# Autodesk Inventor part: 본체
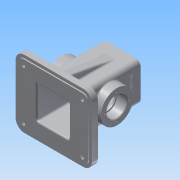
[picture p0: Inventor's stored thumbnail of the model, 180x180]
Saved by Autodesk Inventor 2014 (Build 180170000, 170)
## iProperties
Created: 2015-12
Part Number: 본체
Material: 알루미늄 6061
Document SubType Name: Modeling
Designer: Administrator
Density: 2.71 g/cm^3
Appearance: 알루미늄 - 평지
Mass: 913.38 g
Surface Area: 966.963 cm^2
Volume: 337.041 cm^3
Author: Administrator
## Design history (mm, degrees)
sketch "스케치1"
  geometry: L1 (32.5, 55)-(-32.5, 55); L2 (-32.5, 55)-(-32.5, -55); L3 (-32.5, -55)-(32.5, -55); L4 (32.5, -55)-(32.5, 55); L5 (32.5, 55)-(-32.5, -55); L6 (-32.5, 55)-(32.5, -55); 1 further point
  constraints: 12 end point, 2 midpoint, 2 parallel, 1 horizontal, 1 perpendicular
  dimensions: "d0" = 65 distance of L3.end L2.end; "d1" = 110 distance of L2.end L1.end
extrude "돌출1" new body sketch "스케치1" stored distance "d2" = 65; taper "d3" = 0 deg
sketch "스케치2"
  geometry: C1 r 20 at (32.5, 32.5); 1 further point
  constraints: 1 centre point, 1 coincident
  dimensions: "d4" = 40 diameter of C1
extrude "돌출2" join sketch "스케치2" distance "d5" = 10; taper "d6" = 0 deg
sketch "스케치3"
  geometry: L1 (50, 27.5)-(-55, 27.5); L2 (-55, 27.5)-(-55, -27.5); L3 (-55, -27.5)-(50, -27.5); L4 (50, -27.5)-(50, 27.5); L5 (-55, -32.5)-(-55, 32.5) reference; 3 further points
  constraints: 8 end point, 3 midpoint, 2 parallel, 1 horizontal, 1 horizontal alignment, 1 perpendicular
  dimensions: "d9" = 105 distance of L3.end L2.end; "d10" = 55 distance of L2.end L1.end
extrude "돌출3" cut sketch "스케치3" stored distance "d11" = 55; taper "d12" = 0 deg
sketch "스케치4"
  geometry: C1 r 20 at (0, 0) reference; C2 r 10.5 at (0, 0)
  constraints: 1 centre point, 1 coincident
  dimensions: "d13" = 21 diameter of C2
extrude "돌출4" cut sketch "스케치4" stored distance "d14" = 55; taper "d15" = 0 deg
sketch "스케치5"
  geometry: C1 r 27.5 at (-32.5, 55); 1 further point
  constraints: 1 centre point, 1 coincident
  dimensions: "d16" = 55 diameter of C1
extrude "돌출5" join sketch "스케치5" distance "d17" = 15; taper "d18" = 0 deg
sketch "스케치6" dims "d19" = 42
  geometry: C1 r 27.5 at (0, 0) reference; 2 further points
  constraints: 1 coincident, 1 vertical alignment, 2 other
hole "구멍1" sketch "스케치6" at (0, 21) diameter "d20" = 3.242; stored, may be unused: countersink angle "d24" = 90 deg, drill point angle "d26" = 118 deg; dims "d21" = 8, "d22" = 4, "d23" = 2, "d25" = 10
sketch "스케치7"
  geometry: C1 r 27.5 at (0, 0) reference; C2 r 17.5 at (0, 0)
  constraints: 1 centre point, 1 coincident
  dimensions: "d30" = 35 diameter of C2
extrude "돌출6" cut sketch "스케치7" distance "d31" = 17; taper "d32" = 0 deg
sketch "스케치8"
  geometry: C1 r 17.5 at (0, 0) reference; C2 r 15 at (0, 0)
  constraints: 1 centre point, 1 coincident
  dimensions: "d33" = 30 diameter of C2
extrude "돌출7" cut sketch "스케치8" stored distance "d34" = 17; taper "d35" = 0 deg
sketch "스케치11" dims "d36" = 29
  geometry: C1 r 20 at (0, 0) reference; 2 further points
  constraints: 1 coincident, 1 vertical alignment, 2 other
hole "구멍2" sketch "스케치11" at (0, 14.5) diameter "d37" = 2.459; stored, may be unused: countersink angle "d41" = 90 deg, drill point angle "d43" = 118 deg; dims "d38" = 8, "d39" = 4, "d40" = 2, "d42" = 10
node "작업 평면1"
sketch "스케치14"
  geometry: L1 (-65, 57.5)-(65, 57.5); L2 (65, 57.5)-(65, -57.5); L3 (65, -57.5)-(-65, -57.5); L4 (-65, -57.5)-(-65, 57.5); L5 (-65, 57.5)-(65, -57.5); L6 (65, 57.5)-(-65, -57.5); 1 further point
  constraints: 12 end point, 2 midpoint, 2 parallel, 1 horizontal, 1 perpendicular
  dimensions: "d50" = 130 distance of L2.end L3.end; "d51" = 115 distance of L1.end L2.end
extrude "돌출8" join sketch "스케치14" distance "d52" = 10; taper "d53" = 0 deg
sketch "스케치15"
  geometry: L1 (60, 52.5)-(-60, 52.5); L2 (-60, 52.5)-(-60, -52.5); L3 (-60, -52.5)-(60, -52.5); L4 (60, -52.5)-(60, 52.5); L5 (60, 52.5)-(-60, -52.5); L6 (-60, 52.5)-(60, -52.5); 1 further point
  constraints: 12 end point, 2 midpoint, 2 parallel, 1 horizontal, 1 perpendicular
  dimensions: "d54" = 120 distance of L3.end L2.end; "d55" = 105 distance of L2.end L1.end
extrude "돌출9" join sketch "스케치15" distance "d56" = 2; taper "d57" = 0 deg
fillet "모깎기1" dims "d59" = 15
sketch "스케치17"
  geometry: C1 r 7.5 at (-50, 42.5); C2 r 7.5 at (50, 42.5); C3 r 7.5 at (-50, -42.5); C4 r 7.5 at (50, -42.5); A1 r 15 centre (-50, 42.5) between (-50, 57.5) and (-65, 42.5) reference; A2 r 15 centre (-50, -42.5) between (-65, -42.5) and (-50, -57.5) reference; A3 r 15 centre (50, -42.5) between (50, -57.5) and (65, -42.5) reference; A4 r 15 centre (50, 42.5) between (65, 42.5) and (50, 57.5) reference; 1 further point
  constraints: 4 centre point, 4 coincident
  dimensions: "d60" = 15 diameter of C1; "d61" = 15 diameter of C2; "d62" = 15 diameter of C3; "d63" = 15 diameter of C4
extrude "돌출10" join sketch "스케치17" distance "d64" = 3; taper "d65" = 0 deg
sketch "스케치18"
  geometry: C1 r 7.5 at (0, 0) reference; C2 r 3 at (0, 0); 1 further point
  constraints: 1 centre point, 1 coincident
  dimensions: "d66" = 6 diameter of C2
extrude "돌출11" cut sketch "스케치18" stored distance "d67" = 3; taper "d68" = 0 deg
sketch "스케치19"
  geometry: C1 r 7.5 at (0, 0) reference; C2 r 3 at (0, 0); 1 further point
  constraints: 1 centre point, 1 coincident
  dimensions: "d69" = 6 diameter of C2
extrude "돌출12" cut sketch "스케치19" stored distance "d70" = 3; taper "d71" = 0 deg
sketch "스케치21"
  geometry: L1 (65, -20)-(55, -20) reference; L2 (55, -20)-(55, -32.5) reference; L3 (55, -32.5)-(-50, -32.5) reference; L4 (-50, -32.5)-(-50, -57.5) reference; L5 (-50, -57.5)-(-60, -57.5) reference; L6 (-60, -57.5)-(-60, -52.5) reference; L7 (-60, -52.5)-(-62, -52.5) reference; L8 (-62, -52.5)-(-62, 52.5) reference; L9 (-62, 52.5)-(-60, 52.5) reference; L10 (-60, 52.5)-(-60, 57.5) reference; L11 (-60, 57.5)-(-50, 57.5) reference; L12 (-50, 57.5)-(-50, 32.5) reference; L13 (-50, 32.5)-(55, 32.5) reference; L14 (55, 32.5)-(55, 20) reference; L15 (55, 20)-(65, 20) reference; L16 (65, 20)-(65, 15.73) reference; L17 (65, 15.73)-(55, 15.73) reference; L18 (55, 15.73)-(54.261, 14.5) reference; L19 (54.261, 14.5)-(55, 13.271) reference; L20 (55, 13.271)-(65, 13.271) reference; L21 (65, 13.271)-(65, 10.5) reference; L22 (65, 10.5)-(50, 10.5) reference; L23 (50, 10.5)-(50, 27.5) reference; L24 (50, 27.5)-(-50, 27.5) reference; L25 (-50, 27.5)-(-50, -27.5) reference; L26 (-50, -27.5)-(50, -27.5) reference; L27 (50, -27.5)-(50, -10.5) reference; L28 (50, -10.5)-(65, -10.5) reference; L29 (65, -10.5)-(65, -13.271) reference; L30 (65, -13.271)-(55, -13.271) reference; L31 (55, -13.271)-(54.261, -14.5) reference; L32 (54.261, -14.5)-(55, -15.73) reference; L33 (55, -15.73)-(65, -15.73) reference; L34 (65, -15.73)-(65, -20) reference; L35 (-50, 57.5)-(-50, 47.5); L36 (-50, 47.5)-(35.069, 32.5); 1 further point
  constraints: 4 end point, 2 point on line
  dimensions: "d77" = 10 distance of L11.end L35.end; "d78" = 80 deg angle of L12 L36
extrude "돌출13" join sketch "스케치21" stored distance "d79" = 15; taper "d80" = 0 deg
fillet "모깎기2" dims "d81" = 10
sketch "스케치22"
  geometry: L1 (-37.5, -22.621)-(-36.526, -21) reference; L2 (-36.526, -21)-(-37.5, -19.379) reference; L3 (-37.5, -19.379)-(-47.5, -19.379) reference; L4 (-47.5, -19.379)-(-47.5, -17.5) reference; L5 (-47.5, -17.5)-(-30.5, -17.5) reference; L6 (-30.5, -17.5)-(-30.5, -15) reference; L7 (-30.5, -15)-(-27.5, -15) reference; L8 (-27.5, -15)-(-27.5, -50) reference; L9 (-27.5, -50)-(27.5, -50) reference; L10 (27.5, -50)-(27.5, -15) reference; L11 (27.5, -15)-(30.5, -15) reference; L12 (30.5, -15)-(30.5, -17.5) reference; L13 (30.5, -17.5)-(47.5, -17.5) reference; L14 (47.5, -17.5)-(47.5, -19.379) reference; L15 (47.5, -19.379)-(37.5, -19.379) reference; L16 (37.5, -19.379)-(36.526, -21) reference; L17 (36.526, -21)-(37.5, -22.621) reference; L18 (37.5, -22.621)-(47.5, -22.621) reference; L19 (47.5, -22.621)-(47.5, -27.5) reference; L20 (47.5, -27.5)-(32.5, -27.5) reference; L21 (32.5, -27.5)-(32.5, -50) reference; L22 (32.5, -50)-(65, -50) reference; L23 (65, -50)-(65, -60) reference; L24 (65, -60)-(60, -60) reference; L25 (60, -60)-(60, -62) reference; L26 (60, -62)-(-60, -62) reference; L27 (-60, -62)-(-60, -60) reference; L28 (-60, -60)-(-65, -60) reference; L29 (-65, -60)-(-65, -50) reference; L30 (-65, -50)-(-32.5, -50) reference; L31 (-32.5, -50)-(-32.5, -27.5) reference; L32 (-32.5, -27.5)-(-47.5, -27.5) reference; L33 (-47.5, -27.5)-(-47.5, -22.621) reference; L34 (-47.5, -22.621)-(-37.5, -22.621) reference; L35 (-20, 55)-(-20, 65) reference; L36 (-20, 65)-(-15.729, 65) reference; L37 (-15.729, 65)-(-15.729, 55) reference; L38 (-15.729, 55)-(-14.5, 54.261) reference; L39 (-14.5, 54.261)-(-13.27, 55) reference; L40 (-13.27, 55)-(-13.27, 65) reference; L41 (-13.27, 65)-(-10.5, 65) reference; L42 (-10.5, 65)-(-10.5, 50) reference; L43 (-10.5, 50)-(-27.5, 50) reference; L44 (-27.5, 50)-(-27.5, 15) reference; L45 (-27.5, 15)-(-30.5, 15) reference; L46 (-30.5, 15)-(-30.5, 17.5) reference; L47 (-30.5, 17.5)-(-47.5, 17.5) reference; L48 (-47.5, 17.5)-(-47.5, 19.379) reference; L49 (-47.5, 19.379)-(-37.5, 19.379) reference; L50 (-37.5, 19.379)-(-36.526, 21) reference; L51 (-36.526, 21)-(-37.5, 22.621) reference; L52 (-37.5, 22.621)-(-47.5, 22.621) reference; L53 (-47.5, 22.621)-(-47.5, 27.5) reference; L54 (-47.5, 27.5)-(-32.5, 27.5) reference; L55 (-32.5, 27.5)-(-32.5, 55) reference; L56 (-32.5, 55)-(-20, 55) reference; L57 (20, 65)-(20, 55) reference; L58 (20, 55)-(32.5, 55) reference; L59 (32.5, 55)-(32.5, 27.5) reference; L60 (32.5, 27.5)-(47.5, 27.5) reference; L61 (47.5, 27.5)-(47.5, 22.621) reference; L62 (47.5, 22.621)-(37.5, 22.621) reference; L63 (37.5, 22.621)-(36.526, 21) reference; L64 (36.526, 21)-(37.5, 19.379) reference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; 2 further points
  constraints: 10 end point, 3 perpendicular, 2 point on line, 1 parallel
  dimensions: "d82" = 10 distance of L21.end L79.end; "d108" = 34.5 distance between parallel lines of L23 L82; "d109" = 34.46005 distance between parallel lines of L24 L81; "d110" = 27.5 distance from line of point (37.5, -27.5) L23
  node "절단 모서리 투영3"
fillet "모깎기7" dims "d93" = 3
sketch "스케치23"
  geometry: L1 (-27.5, 27.5)-(27.5, 27.5); L2 (27.5, 27.5)-(27.5, -27.5); L3 (27.5, -27.5)-(-27.5, -27.5); L4 (-27.5, -27.5)-(-27.5, 27.5); L5 (-27.5, 27.5)-(27.5, -27.5); L6 (27.5, 27.5)-(-27.5, -27.5); 1 further point
  constraints: 12 end point, 2 midpoint, 2 parallel, 1 horizontal, 1 perpendicular
  dimensions: "d98" = 55 distance of L2.end L3.end; "d99" = 55 distance of L1.end L2.end
extrude "돌출16" cut sketch "스케치23" stored distance "d100" = 5; taper "d101" = 0 deg
fillet "모깎기14" dims "d104" = 8
fillet "모깎기15" dims "d105" = 0.3
fillet "모깎기16" dims "d106" = 3
fillet "모깎기17" dims "d107" = 3
extrude "돌출17" join sketch "스케치22" stored distance "d111" = 6; taper "d112" = 0 deg
fillet "모깎기18" dims "d113" = 3
fillet "모깎기19" dims "d114" = 3
fillet "모깎기20" dims "d115" = 3
fillet "모깎기21" dims "d116" = 3
sketch "스케치24"
  geometry: L1 (77, -117)-(-28, -117) reference; L2 (-28, -117)-(-28, -115) reference; L3 (-28, -115)-(-33, -115) reference; L4 (-33, -115)-(-33, -105) reference; L5 (-33, -105)-(-7.55, -105) reference; L6 (18.5, -102)-(0, -102) reference; L7 (18.5, -84.904)-(18.5, -102) reference; L8 (0, -102)-(0, -73.166) reference; L9 (77, -115)-(77, -117) reference; L10 (82, -115)-(77, -115) reference; L11 (82, -105)-(82, -115) reference; L12 (56.55, -105)-(82, -105) reference; L13 (49, -73.166)-(49, -102) reference; L14 (30.5, -102)-(30.5, -84.904) reference; L15 (49, -102)-(30.5, -102) reference; L16 (49, 0)-(49, -36.834) reference; L17 (0, 0)-(49, 0) reference; L18 (0, -36.834)-(0, 0) reference; L19 (-8, 0)-(-8, -102) reference; L20 (44.5, 10)-(4.5, 10) reference; C1 r 17.5 at (24.5, -55) reference; A1 r 30.5 centre (24.5, -55) between (0, -73.166) and (18.5, -84.904) reference; A2 r 30.5 centre (24.5, -55) between (30.5, -84.904) and (49, -73.166) reference; A3 r 30.5 centre (24.5, -55) between (49, -36.834) and (0, -36.834) reference; 1 further point
  constraints: 2 vertical alignment, 3 other
  dimensions: "d117" = 32.5 distance from line of L19 point (24.5, -16); "d118" = 26 distance from line of L20 point (24.5, -16)
feature "엠보싱1" sketch "스케치24" dims "d119" = 0.5, "d120" = 0
chamfer "모따기1" distance "d121" = 1; stored, may be unused: second distance "d122" = 2, angle "d123" = 45 deg
fillet "모깎기22" dims "d124" = 3
node "솔리드1"
pattern_circular "원형 패턴1" dims angle "d28" = 360 deg
pattern_circular "원형 패턴2" dims angle "d45" = 360 deg
mirror "대칭1"
mirror "대칭2"
mirror "대칭3"
mirror "대칭5"
node "절단 모서리 투영2"
node "절단 모서리 투영4"
